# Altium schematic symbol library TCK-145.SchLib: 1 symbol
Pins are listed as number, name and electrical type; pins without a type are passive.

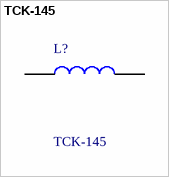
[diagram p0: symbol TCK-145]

## TCK-145
designator L?
Fixed Inductors Inductor 6.8uH 1A 300mOhm; Manufacturer_Name: Traco Power; Geometry.Height: 2.6mm
footprint TCK145
pins: 1, 2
